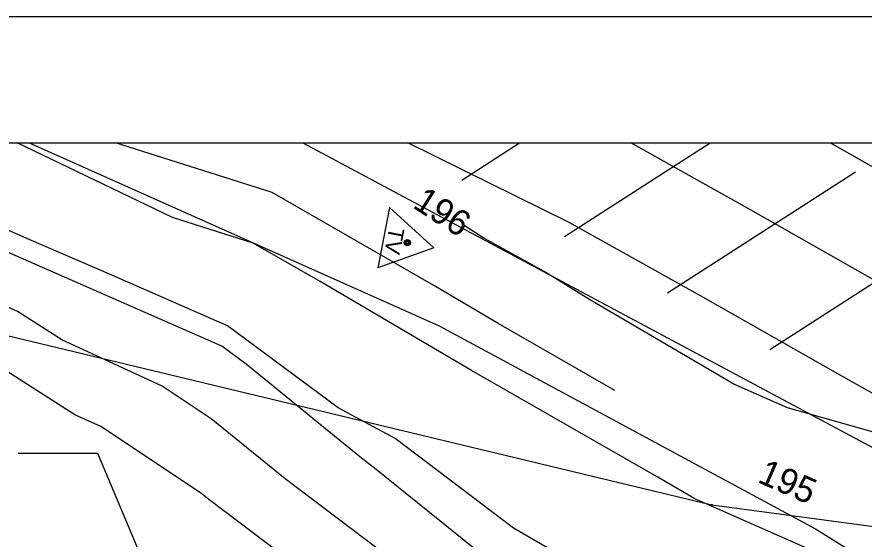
# Model space of a CAD drawing. Extents: x 1385284 to 1385995, y 1975154 to 1975620.
# Drawn here: x 1385448.7 to 1385530.9, y 1975569 to 1975619.6 of the extents above; entities that cross this region are included whole.
import ezdxf

# ---------------------------------------------------------------- set-up
doc = ezdxf.new("R2010")
doc.units = 0
for name, color, linetype in [('1', 7, 'Continuous'), ('Default', 7, 'Continuous'), ('DTM CONTOURS_MAJOR', 7, 'Continuous'), ('DTM_CONTOURS_MINOR', 7, 'Continuous'), ('R_Prop Surface', 7, 'Continuous'), ('S_BASELINE', 7, 'Continuous'), ('S_EDGE_PAVEMENT', 7, 'Continuous'), ('S_PAVEMENT_CROWN', 7, 'Continuous'), ('S_SECONDARY_CTL', 7, 'Continuous'), ('S_UNDERGROUND_CABLE', 7, 'Continuous'), ('S_UTL_PT_SYM', 7, 'Continuous'), ('S_WATER_UTILITIES', 7, 'Continuous')]:
    doc.layers.add(name, color=color, linetype=linetype)

msp = doc.modelspace()

# ---------------------------------------------------------------- linework, layer by layer
at = {"layer": '1'}
msp.add_line((1385315.54, 1975607.406), (1385982.69, 1975607.406), dxfattribs=at)
for points in [[(1385994.751, 1975619.62), (1385283.842, 1975619.62), (1385283.842, 1975153.738), (1385994.751, 1975153.738)], [(1385315.54, 1975165.953), (1385315.54, 1975607.406), (1385810.692, 1975607.406), (1385810.692, 1975586.483), (1385892.572, 1975586.483), (1385892.572, 1975580.3), (1385982.69, 1975580.3), (1385982.69, 1975165.953)]]:
    msp.add_lwpolyline(points, close=True, dxfattribs=at)
at = {"layer": 'Default'}
for p, q in [((1385456.524, 1975577.26), (1385448.774, 1975577.26)), ((1385461.189, 1975566.132), (1385456.524, 1975577.26))]:
    msp.add_line(p, q, dxfattribs=at)
at = {"layer": 'DTM CONTOURS_MAJOR'}
for points in [[(1385506.718, 1975583.358), (1385503.056, 1975585.478), (1385495.392, 1975589.875), (1385489.133, 1975593.545), (1385473.422, 1975602.578), (1385458.216, 1975607.406)], [(1385522.056, 1975554.091), (1385511.021, 1975558.588), (1385498.653, 1975563.634), (1385496.045, 1975565.603), (1385483.372, 1975575.846), (1385482.113, 1975576.798), (1385470.917, 1975585.913), (1385468.561, 1975587.657), (1385452.473, 1975594.716), (1385451.663, 1975595.064), (1385435.988, 1975601.935), (1385435.363, 1975602.12)]]:
    msp.add_lwpolyline(points, dxfattribs=at)
at = {"layer": 'DTM_CONTOURS_MINOR'}
for points in [[(1385539.708, 1975568.446), (1385539.397, 1975568.104), (1385539.548, 1975566.963), (1385534.851, 1975564.048), (1385526.785, 1975567.431), (1385514.475, 1975572.866), (1385510.817, 1975574.983), (1385492.798, 1975585.323), (1385478.08, 1975593.952), (1385471.605, 1975597.675), (1385463.769, 1975600.162), (1385448.691, 1975607.406)], [(1385514.589, 1975561.539), (1385512.543, 1975562.616), (1385501.115, 1975567.556), (1385496.853, 1975569.996), (1385485.373, 1975578.699), (1385479.845, 1975581.695), (1385469.098, 1975589.652), (1385457.886, 1975594.571), (1385449.838, 1975598.029), (1385440.126, 1975602.287), (1385428.54, 1975605.711), (1385423.05, 1975606.119), (1385417.264, 1975606.549), (1385404.449, 1975607.001), (1385394.252, 1975605.116), (1385386.475, 1975604.033), (1385375.432, 1975601.945), (1385366.349, 1975599.957), (1385356.912, 1975595.013), (1385349.735, 1975591.254), (1385341.987, 1975580.912), (1385341.879, 1975572.907)], [(1385488.189, 1975564.366), (1385483.74, 1975567.963), (1385474.707, 1975574.791), (1385467.529, 1975580.634), (1385462.767, 1975583.789), (1385453.007, 1975588.282), (1385448.704, 1975591.02), (1385437.889, 1975595.952), (1385433.309, 1975597.404), (1385425.221, 1975597.918), (1385419.709, 1975599.94), (1385412.905, 1975600.422), (1385407.929, 1975593.394), (1385399.227, 1975591.016), (1385396.775, 1975581.115)], [(1385531.804, 1975579.34), (1385523.454, 1975581.695), (1385518.242, 1975583.98), (1385504.348, 1975592.137), (1385499.827, 1975594.907), (1385493.986, 1975598.155), (1385492.073, 1975599.383)], [(1385534.545, 1975545.92), (1385529.729, 1975545.685), (1385519.689, 1975538.171), (1385502.211, 1975546.507), (1385502.041, 1975546.577), (1385501.882, 1975546.641), (1385484.577, 1975559.699), (1385484.107, 1975560.079), (1385467.301, 1975572.783), (1385466.481, 1975573.451), (1385456.805, 1975579.862), (1385454.291, 1975581.019), (1385445.143, 1975586.839), (1385441.234, 1975588.622), (1385430.98, 1975591.874), (1385429.467, 1975591.97), (1385421.762, 1975594.796), (1385414.234, 1975590.496), (1385407.886, 1975581.531), (1385406.491, 1975581.15), (1385406.184, 1975579.91)]]:
    msp.add_lwpolyline(points, dxfattribs=at)
at = {"layer": 'R_Prop Surface'}
for p, q in [((1385491.846, 1975603.793), (1385497.462, 1975607.406)), ((1385501.83, 1975598.325), (1385515.944, 1975607.406)), ((1385511.813, 1975592.857), (1385530.065, 1975604.6)), ((1385521.748, 1975587.358), (1385539.946, 1975599.067))]:
    msp.add_line(p, q, dxfattribs=at)
at = {"layer": 'S_BASELINE'}
msp.add_line((1385476.399, 1975607.406), (1385611.25, 1975535.294), dxfattribs=at)
at = {"layer": 'S_EDGE_PAVEMENT'}
for points in [[(1385541.434, 1975577.631), (1385528.367, 1975584.998), (1385515.32, 1975592.401), (1385502.266, 1975599.659), (1385486.616, 1975607.406)], [(1385550.856, 1975594.188), (1385537.815, 1975601.599), (1385527.598, 1975607.406)]]:
    msp.add_lwpolyline(points, dxfattribs=at)
at = {"layer": 'S_PAVEMENT_CROWN'}
msp.add_lwpolyline([(1385546.162, 1975585.94), (1385533.126, 1975593.36), (1385520.089, 1975600.78), (1385508.263, 1975607.406)], dxfattribs=at)
at = {"layer": 'S_SECONDARY_CTL'}
for p, q in [((1385484.836, 1975601.121), (1385483.691, 1975595.275)), ((1385489.119, 1975597.215), (1385484.836, 1975601.121)), ((1385489.119, 1975597.215), (1385483.691, 1975595.275))]:
    msp.add_line(p, q, dxfattribs=at)
for radius in [0.311, 0.183, 0.103]:
    msp.add_circle((1385486.557, 1975597.716), radius, dxfattribs=at)
at = {"layer": 'S_UNDERGROUND_CABLE'}
for p, q in [((1385449.857, 1975607.406), (1385489.643, 1975589.637)), ((1385489.643, 1975589.637), (1385526.194, 1975569.941)), ((1385526.194, 1975569.941), (1385618.813, 1975512.534))]:
    msp.add_line(p, q, dxfattribs=at)
at = {"layer": 'S_UTL_PT_SYM'}
msp.add_lwpolyline([(1385516.104, 1975572.278), (1385516.153, 1975572.268), (1385516.104, 1975572.278), (1385516.114, 1975572.327), (1385516.104, 1975572.278), (1385516.055, 1975572.287), (1385516.104, 1975572.278), (1385516.094, 1975572.229)], dxfattribs=at)
at = {"layer": 'S_WATER_UTILITIES'}
for p, q in [((1385373.628, 1975606.526), (1385516.104, 1975572.278)), ((1385516.104, 1975572.278), (1385538.906, 1975569.213))]:
    msp.add_line(p, q, dxfattribs=at)

# ---------------------------------------------------------------- texts
at = {"layer": 'Default'}
for s, rotation, p in [('196', 327.29358, (1385486.958, 1975601.182)), ('195', 336.32708, (1385520.451, 1975574.509))]:
    msp.add_text(s, height=2.5, rotation=rotation, dxfattribs=at).set_placement(p)
at = {"layer": 'S_SECONDARY_CTL'}
msp.add_text('TV', height=1.5, rotation=258.91643, dxfattribs=at).set_placement((1385484.815, 1975599.285))

doc.saveas('drawing.dxf')
